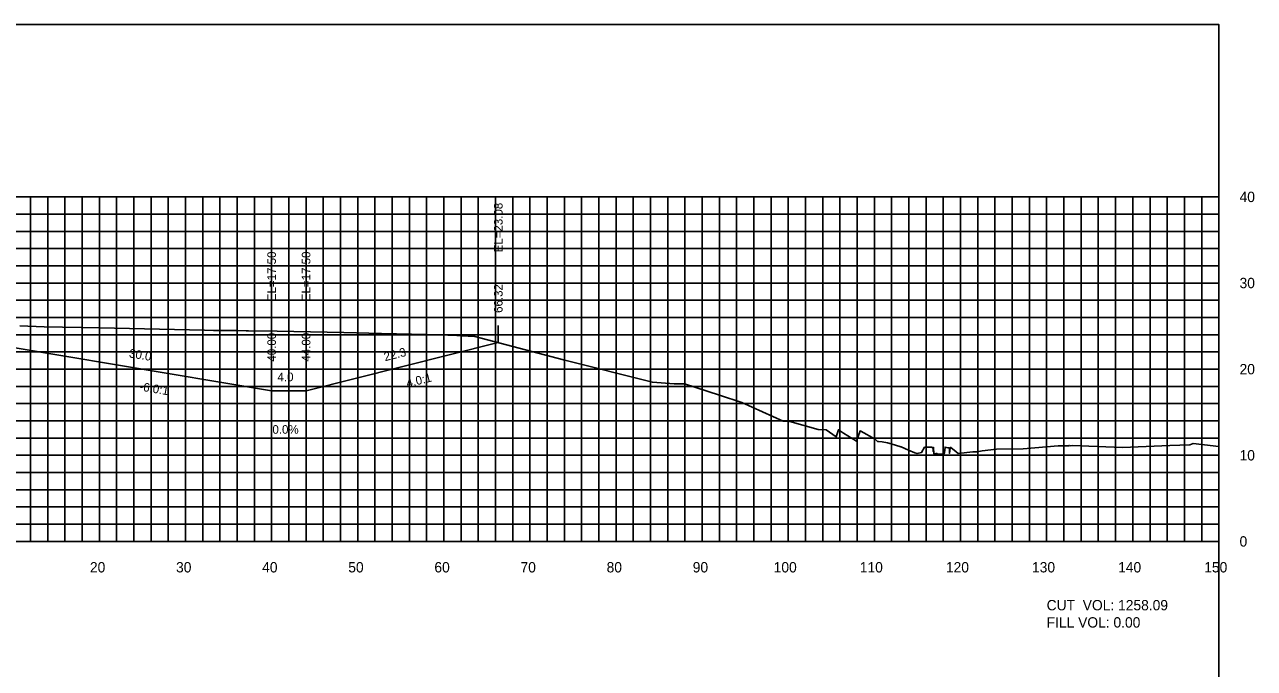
# Model space of a CAD drawing. Extents: x 1800976 to 1805104, y 250057 to 250580.
# Drawn here: x 1802642.3 to 1802785.1, y 250194.7 to 250269.4 of the extents above; entities that cross this region are included whole.
import ezdxf

# ---------------------------------------------------------------- set-up
doc = ezdxf.new("R2010")
doc.units = 0
for name, color, linetype in [('10', 7, 'Continuous'), ('3', 7, 'Continuous'), ('31', 7, 'Continuous'), ('4', 7, 'Continuous'), ('60', 7, 'Continuous'), ('ANNO-TXT', 7, 'Continuous'), ('CL-CNST', 7, 'Continuous'), ('Level 62', 7, 'Continuous'), ('M-ROADS', 7, 'Continuous')]:
    doc.layers.add(name, color=color, linetype=linetype)

msp = doc.modelspace()

# ---------------------------------------------------------------- linework, layer by layer
for p, q in [((1802697.32, 250232.51), (1802697.32, 250234.51)), ((1802671, 250226.93), (1802671, 250228.93)), ((1802675, 250226.93), (1802675, 250228.93))]:
    msp.add_line(p, q)
msp.add_lwpolyline([(1802481, 250079.43), (1802781, 250079.43), (1802781, 250269.43), (1802481, 250269.43)], close=True)
at = {"layer": '60'}
for p, q in [((1802781, 250209.43), (1802781, 250249.43)), ((1802781.06, 250249.43), (1802781, 250249.43)), ((1802781.06, 250239.43), (1802781, 250239.43)), ((1802781.06, 250229.43), (1802781, 250229.43)), ((1802781.06, 250219.43), (1802781, 250219.43)), ((1802481, 250209.43), (1802781, 250209.43)), ((1802651, 250209.37), (1802651, 250209.43)), ((1802661, 250209.37), (1802661, 250209.43)), ((1802671, 250209.37), (1802671, 250209.43)), ((1802681, 250209.37), (1802681, 250209.43)), ((1802691, 250209.37), (1802691, 250209.43)), ((1802701, 250209.37), (1802701, 250209.43)), ((1802711, 250209.37), (1802711, 250209.43)), ((1802721, 250209.37), (1802721, 250209.43)), ((1802731, 250209.37), (1802731, 250209.43)), ((1802741, 250209.37), (1802741, 250209.43)), ((1802751, 250209.37), (1802751, 250209.43)), ((1802761, 250209.37), (1802761, 250209.43)), ((1802771, 250209.37), (1802771, 250209.43)), ((1802781, 250209.37), (1802781, 250209.43)), ((1802781.06, 250209.43), (1802781, 250209.43))]:
    msp.add_line(p, q, dxfattribs=at)
at = {"layer": 'CL-CNST'}
msp.add_lwpolyline([(1802593, 250231.54), (1802599, 250232.54), (1802601, 250232.62), (1802607, 250232.86), (1802631, 250232.33), (1802639, 250232.01), (1802641, 250231.93), (1802671, 250226.93), (1802675, 250226.93), (1802697.32, 250232.51)], dxfattribs=at)
at = {"layer": 'Level 62'}
for p, q in [((1802481, 250249.43), (1802781, 250249.43)), ((1802643, 250209.43), (1802643, 250249.43)), ((1802645, 250209.43), (1802645, 250249.43)), ((1802647, 250209.43), (1802647, 250249.43)), ((1802649, 250209.43), (1802649, 250249.43)), ((1802651, 250209.43), (1802651, 250249.43)), ((1802653, 250209.43), (1802653, 250249.43)), ((1802655, 250209.43), (1802655, 250249.43)), ((1802657, 250209.43), (1802657, 250249.43)), ((1802659, 250209.43), (1802659, 250249.43)), ((1802661, 250209.43), (1802661, 250249.43)), ((1802663, 250209.43), (1802663, 250249.43)), ((1802665, 250209.43), (1802665, 250249.43)), ((1802667, 250209.43), (1802667, 250249.43)), ((1802669, 250209.43), (1802669, 250249.43)), ((1802671, 250209.43), (1802671, 250249.43)), ((1802673, 250209.43), (1802673, 250249.43)), ((1802675, 250209.43), (1802675, 250249.43)), ((1802677, 250209.43), (1802677, 250249.43)), ((1802679, 250209.43), (1802679, 250249.43)), ((1802681, 250209.43), (1802681, 250249.43)), ((1802683, 250209.43), (1802683, 250249.43)), ((1802685, 250209.43), (1802685, 250249.43)), ((1802687, 250209.43), (1802687, 250249.43)), ((1802689, 250209.43), (1802689, 250249.43)), ((1802691, 250209.43), (1802691, 250249.43)), ((1802693, 250209.43), (1802693, 250249.43)), ((1802695, 250209.43), (1802695, 250249.43)), ((1802697, 250209.43), (1802697, 250249.43)), ((1802699, 250209.43), (1802699, 250249.43)), ((1802701, 250209.43), (1802701, 250249.43)), ((1802703, 250209.43), (1802703, 250249.43)), ((1802705, 250209.43), (1802705, 250249.43)), ((1802707, 250209.43), (1802707, 250249.43)), ((1802709, 250209.43), (1802709, 250249.43)), ((1802711, 250209.43), (1802711, 250249.43)), ((1802713, 250209.43), (1802713, 250249.43)), ((1802715, 250209.43), (1802715, 250249.43)), ((1802717, 250209.43), (1802717, 250249.43)), ((1802719, 250209.43), (1802719, 250249.43)), ((1802721, 250209.43), (1802721, 250249.43)), ((1802723, 250209.43), (1802723, 250249.43)), ((1802725, 250209.43), (1802725, 250249.43)), ((1802727, 250209.43), (1802727, 250249.43)), ((1802729, 250209.43), (1802729, 250249.43)), ((1802731, 250209.43), (1802731, 250249.43)), ((1802733, 250209.43), (1802733, 250249.43)), ((1802735, 250209.43), (1802735, 250249.43)), ((1802737, 250209.43), (1802737, 250249.43)), ((1802739, 250209.43), (1802739, 250249.43)), ((1802741, 250209.43), (1802741, 250249.43)), ((1802743, 250209.43), (1802743, 250249.43)), ((1802745, 250209.43), (1802745, 250249.43)), ((1802747, 250209.43), (1802747, 250249.43)), ((1802749, 250209.43), (1802749, 250249.43)), ((1802751, 250209.43), (1802751, 250249.43)), ((1802753, 250209.43), (1802753, 250249.43)), ((1802755, 250209.43), (1802755, 250249.43)), ((1802757, 250209.43), (1802757, 250249.43)), ((1802759, 250209.43), (1802759, 250249.43)), ((1802761, 250209.43), (1802761, 250249.43)), ((1802763, 250209.43), (1802763, 250249.43)), ((1802765, 250209.43), (1802765, 250249.43)), ((1802767, 250209.43), (1802767, 250249.43)), ((1802769, 250209.43), (1802769, 250249.43)), ((1802771, 250209.43), (1802771, 250249.43)), ((1802773, 250209.43), (1802773, 250249.43)), ((1802775, 250209.43), (1802775, 250249.43)), ((1802777, 250209.43), (1802777, 250249.43)), ((1802779, 250209.43), (1802779, 250249.43)), ((1802781, 250209.43), (1802781, 250249.43)), ((1802481, 250247.43), (1802781, 250247.43)), ((1802481, 250245.43), (1802781, 250245.43)), ((1802481, 250243.43), (1802781, 250243.43)), ((1802481, 250241.43), (1802781, 250241.43)), ((1802481, 250239.43), (1802781, 250239.43)), ((1802481, 250237.43), (1802781, 250237.43)), ((1802481, 250235.43), (1802781, 250235.43)), ((1802481, 250233.43), (1802781, 250233.43)), ((1802481, 250231.43), (1802781, 250231.43)), ((1802481, 250229.43), (1802781, 250229.43)), ((1802481, 250227.43), (1802781, 250227.43)), ((1802481, 250225.43), (1802781, 250225.43)), ((1802481, 250223.43), (1802781, 250223.43)), ((1802481, 250221.43), (1802781, 250221.43)), ((1802481, 250219.43), (1802781, 250219.43)), ((1802481, 250217.43), (1802781, 250217.43)), ((1802481, 250215.43), (1802781, 250215.43)), ((1802481, 250213.43), (1802781, 250213.43)), ((1802481, 250211.43), (1802781, 250211.43)), ((1802481, 250209.43), (1802781, 250209.43))]:
    msp.add_line(p, q, dxfattribs=at)
at = {"layer": 'M-ROADS'}
msp.add_lwpolyline([(1802641.74, 250234.45), (1802644.59, 250234.36), (1802651.01, 250234.22), (1802663.2, 250233.94), (1802664.24, 250233.93), (1802667.05, 250233.9), (1802668.05, 250233.89), (1802668.3, 250233.89), (1802671.65, 250233.83), (1802679.38, 250233.68), (1802683.76, 250233.57), (1802690.76, 250233.41), (1802691.48, 250233.38), (1802692.01, 250233.36), (1802693.01, 250233.31), (1802694.6, 250233.22), (1802704.91, 250230.51), (1802715.21, 250227.91), (1802717.75, 250227.71), (1802718.49, 250227.71), (1802718.95, 250227.71), (1802723, 250226.4), (1802725.6, 250225.56), (1802730.39, 250223.41), (1802731.17, 250223.37), (1802734.48, 250222.43), (1802735.4, 250222.39), (1802736.54, 250221.57), (1802736.82, 250222.39), (1802737.42, 250222.01), (1802738.93, 250221.05), (1802739.33, 250222.25), (1802739.43, 250222.22), (1802741.08, 250221.32), (1802741.35, 250221.04), (1802741.46, 250221.04), (1802741.9, 250220.98), (1802742.5, 250220.87), (1802742.93, 250220.75), (1802744.07, 250220.43), (1802744.12, 250220.43), (1802744.94, 250220.03), (1802745.69, 250219.71), (1802745.96, 250219.62), (1802746.47, 250219.76), (1802746.82, 250220.36), (1802747.18, 250220.39), (1802747.61, 250220.36), (1802747.7, 250220.36), (1802747.75, 250220.31), (1802747.78, 250220.3), (1802747.83, 250220.1), (1802747.83, 250219.86), (1802747.85, 250220.24), (1802747.86, 250220.34), (1802747.89, 250219.61), (1802747.9, 250219.59), (1802748.13, 250219.62), (1802748.26, 250219.63), (1802748.26, 250219.64), (1802748.26, 250219.64), (1802748.28, 250219.5), (1802748.29, 250219.52), (1802748.32, 250219.56), (1802748.37, 250219.55), (1802748.48, 250219.55), (1802748.68, 250219.56), (1802749.07, 250219.6), (1802749.14, 250219.72), (1802749.21, 250220.39), (1802749.52, 250220.31), (1802749.68, 250220.29), (1802749.71, 250220.06), (1802749.73, 250220.17), (1802749.73, 250219.65), (1802749.81, 250220.31), (1802749.81, 250220.35), (1802749.82, 250220.29), (1802749.83, 250220.34), (1802749.86, 250220.33), (1802750.51, 250219.82), (1802750.74, 250219.62), (1802752.42, 250219.84), (1802752.94, 250219.84), (1802753.5, 250219.94), (1802755.17, 250220.13), (1802758.26, 250220.19), (1802762.33, 250220.54), (1802763.54, 250220.54), (1802763.61, 250220.58), (1802763.73, 250220.54), (1802763.97, 250220.55), (1802769.8, 250220.35), (1802775.31, 250220.57), (1802777.63, 250220.66), (1802778.02, 250220.79), (1802781, 250220.46)], dxfattribs=at)

# ---------------------------------------------------------------- texts
for s, rotation, p in [('4.0:1', 14.0362, (1802686.77, 250227.29)), ('-6.0:1', 350.5377, (1802655.59, 250226.96))]:
    msp.add_text(s, height=1, rotation=rotation).set_placement(p)
at = {"layer": '10'}
for s, p in [('20', (1802649.9, 250205.83)), ('30', (1802659.9, 250205.83)), ('40', (1802669.9, 250205.83)), ('50', (1802679.9, 250205.83)), ('60', (1802689.9, 250205.83)), ('70', (1802699.9, 250205.83)), ('80', (1802709.9, 250205.83)), ('90', (1802719.9, 250205.83)), ('100', (1802729.3, 250205.83)), ('110', (1802739.3, 250205.83)), ('120', (1802749.3, 250205.83)), ('130', (1802759.3, 250205.83)), ('140', (1802769.3, 250205.83)), ('150', (1802779.3, 250205.83))]:
    msp.add_text(s, height=1.2, dxfattribs=at).set_placement(p)
at = {"layer": '3'}
for s, p in [('EL=23.08', (1802697.82, 250242.98)), ('EL=17.50', (1802671.5, 250237.32)), ('EL=17.50', (1802675.5, 250237.32)), ('66.32', (1802697.82, 250235.96)), ('40.00', (1802671.5, 250230.3)), ('44.00', (1802675.5, 250230.3))]:
    msp.add_text(s, height=1, rotation=90, dxfattribs=at).set_placement(p)
at = {"layer": '31'}
for s, p in [('40', (1802783.4, 250248.83)), ('30', (1802783.4, 250238.83)), ('20', (1802783.4, 250228.83)), ('10', (1802783.4, 250218.83)), ('0', (1802783.4, 250208.83))]:
    msp.add_text(s, height=1.2, dxfattribs=at).set_placement(p)
at = {"layer": '4'}
for s, rotation, p in [('30.0', 350.5377, (1802654.39, 250230.81)), ('22.3', 14.0362, (1802684.17, 250230.35))]:
    msp.add_text(s, height=1, rotation=rotation, dxfattribs=at).set_placement(p)
for s, p in [('4.0', (1802671.68, 250228.03)), ('0.0%', (1802671.09, 250221.93))]:
    msp.add_text(s, height=1, dxfattribs=at).set_placement(p)
at = {"layer": 'ANNO-TXT'}
for s, p in [('CUT  VOL: 1258.09', (1802761, 250201.43)), ('FILL VOL: 0.00', (1802761, 250199.43))]:
    msp.add_text(s, height=1.2, dxfattribs=at).set_placement(p)

doc.saveas('drawing.dxf')
